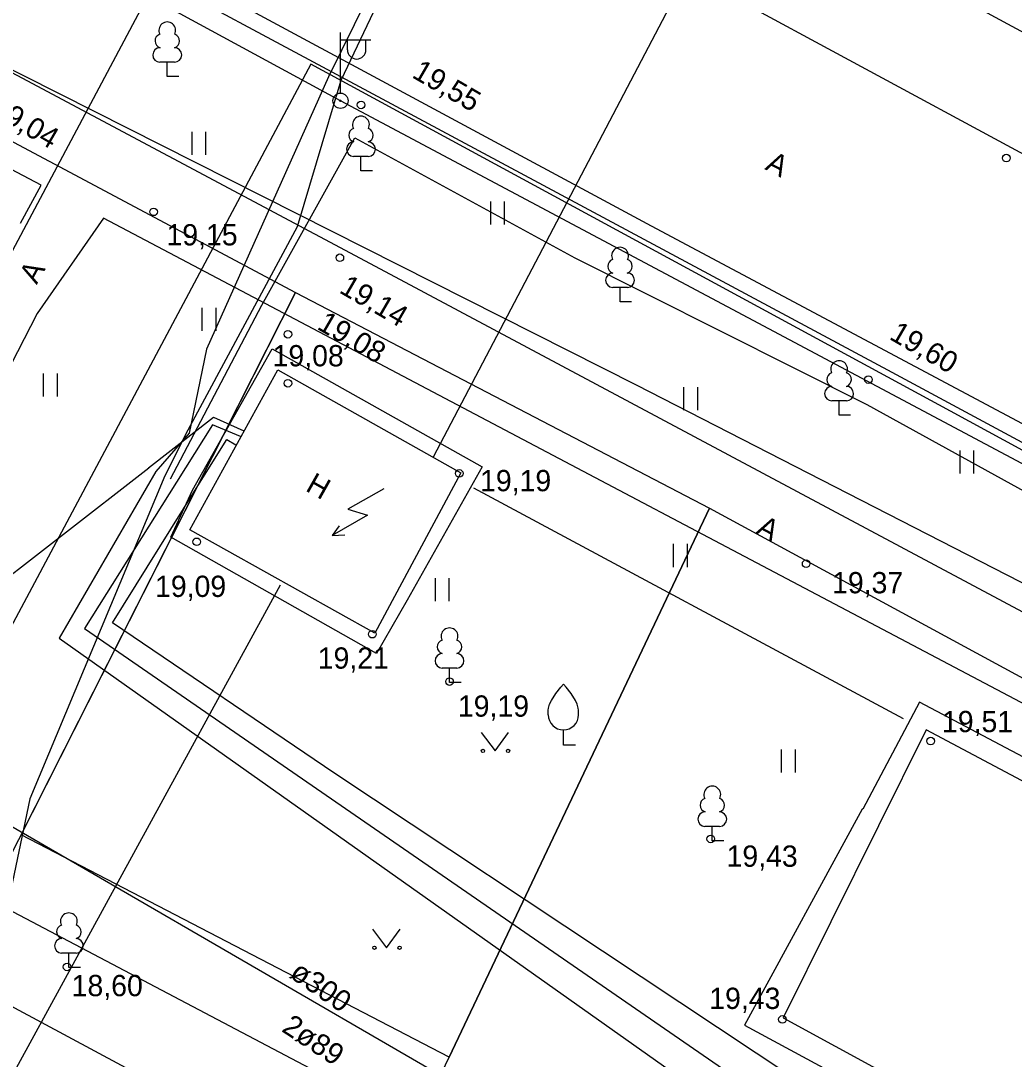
# Model space of a CAD drawing. Extents: x 713497 to 713863, y 6590062 to 6590327.
# Drawn here: x 713764.91 to 713797.61, y 6590124.29 to 6590158.47 of the extents above; entities that cross this region are included whole.
import ezdxf

# ---------------------------------------------------------------- set-up
doc = ezdxf.new("R2010")
doc.units = 0
for name, color, linetype in [('HALJASTUS', 7, 'Continuous'), ('HOONE', 7, 'Continuous'), ('HOONEDET', 7, 'Continuous'), ('KORGUS', 7, 'Continuous'), ('KPKAABEL', 7, 'Continuous'), ('KTRASS', 7, 'Continuous'), ('MPKAABEL', 7, 'Continuous'), ('POST', 7, 'Continuous'), ('PUU', 7, 'Continuous'), ('SITRASS', 7, 'Continuous'), ('TEE', 7, 'Continuous'), ('TORU NR', 7, 'Continuous'), ('TTRASS', 7, 'Continuous'), ('VTRASS', 7, 'Continuous'), ('Слой 1', 7, 'Continuous')]:
    doc.layers.add(name, color=color, linetype=linetype)

msp = doc.modelspace()

# ---------------------------------------------------------------- linework, layer by layer
at = {"layer": 'HALJASTUS'}
for p, q in [((713770.537, 6590154.814), (713770.537, 6590154.052)), ((713770.992, 6590154.814), (713770.992, 6590154.052)), ((713780.366, 6590152.521), (713780.366, 6590151.76)), ((713780.821, 6590152.521), (713780.821, 6590151.76)), ((713770.871, 6590149.021), (713770.871, 6590148.26)), ((713771.326, 6590149.021), (713771.326, 6590148.26)), ((713765.646, 6590146.861), (713765.646, 6590146.1)), ((713766.101, 6590146.861), (713766.101, 6590146.1)), ((713786.726, 6590146.413), (713786.726, 6590145.652)), ((713787.182, 6590146.413), (713787.182, 6590145.652)), ((713795.818, 6590144.326), (713795.818, 6590143.564)), ((713796.273, 6590144.326), (713796.273, 6590143.564)), ((713786.388, 6590141.25), (713786.388, 6590140.489)), ((713786.843, 6590141.25), (713786.843, 6590140.489)), ((713778.546, 6590140.125), (713778.546, 6590139.364)), ((713779.001, 6590140.125), (713779.001, 6590139.364)), ((713780.057, 6590135.047), (713780.52, 6590134.44)), ((713780.52, 6590134.44), (713780.966, 6590135.047)), ((713789.94, 6590134.488), (713789.94, 6590133.727)), ((713790.395, 6590134.488), (713790.395, 6590133.727)), ((713776.487, 6590128.567), (713776.95, 6590127.96)), ((713776.95, 6590127.96), (713777.396, 6590128.567))]:
    msp.add_line(p, q, dxfattribs=at)
msp.add_lwpolyline([(713793.964, 6590135.491), (713779.821, 6590143.089)], dxfattribs=at)
for centre in [(713780.119, 6590134.44), (713780.948, 6590134.44), (713776.549, 6590127.96), (713777.378, 6590127.96)]:
    msp.add_circle(centre, 0.055, dxfattribs=at)
at = {"layer": 'HOONE'}
for p, q in [((713776.858, 6590143.064), (713775.668, 6590142.393)), ((713776.324, 6590142.194), (713775.152, 6590141.527)), ((713775.668, 6590142.393), (713776.324, 6590142.194)), ((713775.386, 6590141.847), (713775.152, 6590141.527)), ((713775.152, 6590141.527), (713775.575, 6590141.546))]:
    msp.add_line(p, q, dxfattribs=at)
for points in [[(713734.713, 6590179.152), (713785.66, 6590151.72), (713826.27, 6590130.08), (713863.358, 6590110.159)], [(713770.476, 6590141.709), (713773.374, 6590146.978), (713779.396, 6590143.591), (713776.564, 6590138.316), (713770.476, 6590141.709)], [(713812.78, 6590105.321), (713821.155, 6590121.073), (713794.711, 6590135.132), (713790, 6590125.65), (713807, 6590116.39), (713803.62, 6590110.13), (713812.78, 6590105.321)], [(713789.29, 6590112.76), (713764.71, 6590125.97), (713755.23, 6590131.21)]]:
    msp.add_lwpolyline(points, dxfattribs=at)
at = {"layer": 'HOONEDET'}
msp.add_lwpolyline([(713814.782, 6590106.918), (713822.414, 6590121.274), (713794.494, 6590136.038), (713792.632, 6590132.516), (713792.607, 6590132.517), (713788.73, 6590125.41), (713801.57, 6590118.48), (713805.74, 6590116.13), (713805.72, 6590115.91), (713802.56, 6590109.88), (713810.794, 6590105.321), (713813.751, 6590103.7)], dxfattribs=at)
at = {"layer": 'KORGUS'}
for centre in [(713776.11, 6590155.7), (713797.35, 6590153.95), (713769.28, 6590152.18), (713775.41, 6590150.67), (713773.7, 6590148.15), (713773.7, 6590146.54), (713792.81, 6590146.66), (713779.34, 6590143.57), (713770.7, 6590141.32), (713790.76, 6590140.6), (713776.48, 6590138.28), (713779.02, 6590136.72), (713794.86, 6590134.76), (713787.62, 6590131.54), (713766.43, 6590127.33), (713789.98, 6590125.6)]:
    msp.add_circle(centre, 0.125, dxfattribs=at)
at = {"layer": 'KPKAABEL'}
for points in [[(713529.988, 6590287.362), (713528.13, 6590283.39), (713562.908, 6590269.342), (713609.57, 6590248.393), (713642.834, 6590233.164), (713665.543, 6590222.669), (713703.801, 6590203.145), (713710.007, 6590200.019), (713735.256, 6590187.298), (713757.247, 6590176.218), (713786.95, 6590160.25), (713778.485, 6590144.103)], [(713794.45, 6590198.59), (713786.13, 6590180.02), (713781.379, 6590168.923), (713780.962, 6590168.239), (713779.091, 6590164.176), (713775.448, 6590156.503), (713774.002, 6590151.688), (713770.408, 6590144.999), (713769.646, 6590143.487), (713765.21, 6590132.86), (713761.14, 6590113.48)], [(713773.44, 6590139.89), (713762.88, 6590120.59), (713775.24, 6590090.28), (713794.548, 6590082.284), (713800.542, 6590079.311), (713832.311, 6590062.302)]]:
    msp.add_lwpolyline(points, dxfattribs=at)
at = {"layer": 'KTRASS'}
msp.add_lwpolyline([(713786.266, 6590164.388), (713813.145, 6590149.856)], dxfattribs=at)
at = {"layer": 'MPKAABEL'}
for points in [[(713831.772, 6590125.699), (713828.625, 6590127.375), (713802.947, 6590141.184), (713775.431, 6590155.836), (713748.262, 6590170.579), (713743.764, 6590161.693), (713741.527, 6590162.242)], [(713781.077, 6590168.981), (713778.842, 6590164.352), (713775.042, 6590156.623), (713771.019, 6590147.665), (713770.454, 6590144.893), (713769.354, 6590143.636), (713766.17, 6590138.15), (713788.39, 6590122.43), (713799.07, 6590115.1), (713794.37, 6590106.34), (713776.17, 6590073.19)], [(713769.832, 6590143.392), (713772.837, 6590149.111), (713775.904, 6590154.621), (713783.15, 6590150.665), (713792.756, 6590145.834), (713802.454, 6590140.499), (713816.774, 6590132.975), (713828.273, 6590126.537), (713829.411, 6590125.567), (713830.253, 6590123.272), (713831.773, 6590121.257), (713837.66, 6590119.057), (713843.1, 6590118.531), (713851.23, 6590114.43), (713852.8, 6590114.122), (713856.379, 6590111.655), (713863.358, 6590107.953)], [(713753.52, 6590136.81), (713757.48, 6590134.71), (713769.123, 6590143.755), (713769.116, 6590143.758), (713771.25, 6590145.42), (713772.245, 6590144.971)], [(713772.142, 6590144.788), (713771.22, 6590145.17), (713770.034, 6590143.288), (713767, 6590138.47), (713790.41, 6590122.33), (713802.69, 6590113.94)], [(713805.5, 6590113.62), (713775.25, 6590133.69), (713767.93, 6590138.65), (713770.628, 6590142.984), (713771.69, 6590144.69), (713771.988, 6590144.513)]]:
    msp.add_lwpolyline(points, dxfattribs=at)
at = {"layer": 'POST'}
for p, q in [((713775.431, 6590156.086), (713775.431, 6590158.086)), ((713775.431, 6590157.836), (713776.431, 6590157.836)), ((713775.658, 6590157.515), (713775.658, 6590157.836)), ((713776.271, 6590157.515), (713776.271, 6590157.836))]:
    msp.add_line(p, q, dxfattribs=at)
for radius in [0.25, 0.0234]:
    msp.add_circle((713775.431, 6590155.836), radius, dxfattribs=at)
msp.add_arc((713775.964, 6590157.515), 0.306, 180, 0, dxfattribs=at)
at = {"layer": 'PUU'}
for p, q in [((713769.968, 6590157.107), (713769.488, 6590157.107)), ((713769.728, 6590156.632), (713769.728, 6590157.107)), ((713770.108, 6590156.632), (713769.728, 6590156.632)), ((713776.345, 6590154.006), (713775.865, 6590154.006)), ((713776.105, 6590153.531), (713776.105, 6590154.006)), ((713776.485, 6590153.531), (713776.105, 6590153.531)), ((713784.875, 6590149.691), (713784.395, 6590149.691)), ((713784.635, 6590149.216), (713784.635, 6590149.691)), ((713785.015, 6590149.216), (713784.635, 6590149.216)), ((713792.086, 6590145.96), (713791.606, 6590145.96)), ((713791.846, 6590145.485), (713791.846, 6590145.96)), ((713792.226, 6590145.485), (713791.846, 6590145.485)), ((713779.26, 6590137.165), (713778.78, 6590137.165)), ((713779.02, 6590136.69), (713779.02, 6590137.165)), ((713779.4, 6590136.69), (713779.02, 6590136.69)), ((713782.77, 6590134.63), (713782.77, 6590135.13)), ((713783.17, 6590134.63), (713782.77, 6590134.63)), ((713787.91, 6590131.955), (713787.43, 6590131.955)), ((713787.67, 6590131.48), (713787.67, 6590131.955)), ((713788.05, 6590131.48), (713787.67, 6590131.48)), ((713766.73, 6590127.785), (713766.25, 6590127.785)), ((713766.49, 6590127.31), (713766.49, 6590127.785)), ((713766.87, 6590127.31), (713766.49, 6590127.31))]:
    msp.add_line(p, q, dxfattribs=at)
for points in [[(713782.27, 6590135.63), (713782.27, 6590135.78), (713782.28, 6590135.845), (713782.315, 6590135.975), (713782.375, 6590136.095), (713782.52, 6590136.33), (713782.68, 6590136.535), (713782.77, 6590136.63)], [(713783.27, 6590135.63), (713783.27, 6590135.78), (713783.26, 6590135.845), (713783.225, 6590135.975), (713783.165, 6590136.095), (713783.02, 6590136.33), (713782.86, 6590136.535), (713782.77, 6590136.63)]]:
    msp.add_lwpolyline(points, dxfattribs=at)
for centre, radius, start, end in [((713769.728, 6590158.152), 0.277, 332.5799, 207.4201), ((713769.558, 6590157.804), 0.233, 109.0217, 253.1415), ((713769.898, 6590157.804), 0.233, 286.8508, 70.9859), ((713769.49, 6590157.344), 0.238, 90.0016, 269.3953), ((713769.965, 6590157.344), 0.238, 270.6047, 89.9984), ((713776.105, 6590155.051), 0.277, 332.5799, 207.4201), ((713775.935, 6590154.704), 0.233, 109.0217, 253.1415), ((713776.275, 6590154.704), 0.233, 286.8508, 70.9859), ((713775.868, 6590154.244), 0.238, 90.0016, 269.3953), ((713776.343, 6590154.244), 0.238, 270.6047, 89.9984), ((713784.635, 6590150.736), 0.277, 332.5799, 207.4201), ((713784.465, 6590150.389), 0.233, 109.0217, 253.1415), ((713784.805, 6590150.389), 0.233, 286.8508, 70.9859), ((713784.398, 6590149.929), 0.238, 90.0016, 269.3953), ((713784.873, 6590149.929), 0.238, 270.6047, 89.9984), ((713791.846, 6590147.005), 0.277, 332.5799, 207.4201), ((713791.675, 6590146.658), 0.233, 109.0217, 253.1415), ((713792.016, 6590146.658), 0.233, 286.8508, 70.9859), ((713791.608, 6590146.198), 0.238, 90.0016, 269.3953), ((713792.083, 6590146.198), 0.238, 270.6047, 89.9984), ((713779.02, 6590138.21), 0.277, 332.5799, 207.4201), ((713778.85, 6590137.863), 0.233, 109.0217, 253.1415), ((713779.19, 6590137.863), 0.233, 286.8508, 70.9859), ((713778.783, 6590137.402), 0.238, 90.0016, 269.3953), ((713779.257, 6590137.402), 0.238, 270.6047, 89.9984), ((713782.77, 6590135.63), 0.5, 180, 0), ((713787.67, 6590133), 0.277, 332.5799, 207.4201), ((713787.5, 6590132.653), 0.233, 109.0217, 253.1415), ((713787.84, 6590132.653), 0.233, 286.8508, 70.9859), ((713787.433, 6590132.192), 0.238, 90.0016, 269.3953), ((713787.907, 6590132.192), 0.238, 270.6047, 89.9984), ((713766.49, 6590128.83), 0.277, 332.5799, 207.4201), ((713766.32, 6590128.483), 0.233, 109.0217, 253.1415), ((713766.66, 6590128.483), 0.233, 286.8508, 70.9859), ((713766.253, 6590128.022), 0.238, 90.0016, 269.3953), ((713766.727, 6590128.022), 0.238, 270.6047, 89.9984)]:
    msp.add_arc(centre, radius, start, end, dxfattribs=at)
at = {"layer": 'SITRASS'}
for points in [[(713761.318, 6590146.366), (713762.03, 6590146.03), (713762.599, 6590147.099), (713773.56, 6590167.68), (713757.589, 6590176.783), (713720.92, 6590195.235), (713722.942, 6590199.176), (713727.49, 6590208.04), (713727.52, 6590208.2), (713727.47, 6590208.33), (713725.65, 6590209.17)], [(713863.358, 6590109.383), (713837.06, 6590123.42), (713818.31, 6590133.22), (713795.51, 6590145.62), (713774.46, 6590157.04), (713767.746, 6590144.461), (713761.9, 6590133.51)], [(713789.24, 6590117.86), (713783.55, 6590120.96), (713761.9, 6590133.51)]]:
    msp.add_lwpolyline(points, dxfattribs=at)
at = {"layer": 'TEE'}
for points in [[(713729.503, 6590195.962), (713814.96, 6590150.045), (713845.029, 6590133.836), (713845.889, 6590131.902), (713844.472, 6590129.05), (713816.858, 6590143.891), (713797.519, 6590154.285), (713778.342, 6590164.655), (713757.415, 6590175.881), (713740.491, 6590185.02), (713731.812, 6590189.692)], [(713828.341, 6590128.138), (713812.872, 6590136.509), (713793.453, 6590146.972), (713774.088, 6590157.345), (713753.397, 6590168.434), (713735.495, 6590177.892), (713731.587, 6590178.663), (713718.885, 6590185.577)], [(713714.408, 6590183.916), (713728.553, 6590176.306), (713734.767, 6590172.751), (713749.989, 6590164.567), (713777.063, 6590150.129), (713827.431, 6590123.235), (713830.119, 6590122.487)], [(713764.892, 6590151.807), (713765.573, 6590153.058), (713752.09, 6590160.174), (713739.105, 6590167.184), (713732.495, 6590170.739), (713731.699, 6590169.26)], [(713840.64, 6590113.44), (713767.635, 6590151.97), (713765.451, 6590148.839), (713764.143, 6590146.308), (713762.11, 6590142.3), (713760.42, 6590143.28)], [(713770.561, 6590143.018), (713773.179, 6590147.673), (713780.09, 6590143.786), (713777.622, 6590139.398), (713776.613, 6590137.644), (713769.851, 6590141.471), (713770.561, 6590143.018)]]:
    msp.add_lwpolyline(points, dxfattribs=at)
at = {"layer": 'TTRASS'}
msp.add_lwpolyline([(713793.78, 6590113.79), (713759.97, 6590131.6)], dxfattribs=at)
at = {"layer": 'VTRASS'}
msp.add_lwpolyline([(713863.358, 6590105.24), (713853.675, 6590110.345), (713840.649, 6590117.222), (713835.698, 6590119.976), (713821.055, 6590128.059), (713815.868, 6590130.724), (713800.871, 6590138.437), (713785.173, 6590146.474), (713766.203, 6590156.055), (713754.925, 6590161.75), (713749.339, 6590164.472)], dxfattribs=at)
at = {"layer": 'Слой 1'}
for points in [[(713749.45, 6590162.59), (713773.95, 6590149.53), (713761.63, 6590125.2), (713737.22, 6590138.32)], [(713787.58, 6590142.43), (713779.01, 6590124.36), (713764.92, 6590131.68), (713773.95, 6590149.53)], [(713824.52, 6590122.4), (713811.57, 6590098.6), (713775.69, 6590117.42), (713779.01, 6590124.36), (713787.58, 6590142.43)]]:
    msp.add_lwpolyline(points, close=True, dxfattribs=at)

# ---------------------------------------------------------------- texts
at = {"layer": 'HOONE'}
msp.add_text('H', height=0.7, rotation=330.6441, dxfattribs=at).set_placement((713774.247, 6590143.016))
at = {"layer": 'KORGUS'}
for s, p in [('19,55', (713777.75, 6590156.624)), ('19,04', (713763.864, 6590155.406)), ('19,14', (713775.355, 6590149.541)), ('19,08', (713774.626, 6590148.343)), ('19,60', (713793.463, 6590148.011))]:
    msp.add_text(s, height=0.7, rotation=329.8372, dxfattribs=at).set_placement(p)
for s, p in [('19,15', (713769.703, 6590151.075)), ('19,08', (713773.196, 6590147.095)), ('19,19', (713780.026, 6590142.985)), ('19,09', (713769.326, 6590139.505)), ('19,37', (713791.613, 6590139.625)), ('19,21', (713774.682, 6590137.145)), ('19,19', (713779.296, 6590135.565)), ('19,51', (713795.232, 6590135.055)), ('19,43', (713788.141, 6590130.625)), ('18,60', (713766.581, 6590126.365)), ('19,43', (713787.571, 6590125.945))]:
    msp.add_text(s, height=0.7, dxfattribs=at).set_placement(p)
at = {"layer": 'TEE'}
for rotation, p in [(332.6626, (713789.377, 6590153.588)), (61.1614, (713765.431, 6590149.766)), (331.9402, (713789.074, 6590141.605))]:
    msp.add_text('A', height=0.7, rotation=rotation, dxfattribs=at).set_placement(p)
at = {"layer": 'TORU NR'}
for s, rotation, p in [('ø300', 325.2803, (713773.718, 6590127.012)), ('2ø89', 326.5409, (713773.463, 6590125.227))]:
    msp.add_text(s, height=0.7, rotation=rotation, dxfattribs=at).set_placement(p)

doc.saveas('drawing.dxf')
